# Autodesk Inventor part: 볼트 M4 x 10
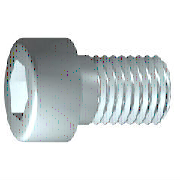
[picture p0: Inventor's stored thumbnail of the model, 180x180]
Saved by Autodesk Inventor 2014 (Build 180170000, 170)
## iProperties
Created: 2012-02
Part Number: 볼트 M4 x 10
Material: 스테인리스강
Description: 6각 소켓 머리 캡 나사
Document SubType Name: Modeling
Standard: ISO 4762
Designer: mduedu
Standard Revision: Fourth edition 2004-03-01
Standards Organization: ISO
Language: ko-KR
Size Designation: M4 x 10
Categories: <MemberInstance><Categories><Category DisplayName="조임쇠" InternalName="e4da775c-781d-43d5-af7c-5136215cf5a6" Mnemonic="FSTN"><Category DisplayName="볼트" InternalN
Density: 8.08 g/cm^3
Appearance: 반광택
IsCustomPart: 0
Author: mduedu
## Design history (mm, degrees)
sketch "스케치1"
  geometry: L1 (-1, 0)-(10, 0); L2 (10, 0)-(10, 2); L3 (10, 2)-(1.75, 2); L4 (1.75, 2)-(1.32, 2); L5 (1.32, 2)-(0, 2); L6 (0, 2)-(0, 3.5); L7 (0, 3.5)-(-4, 3.5); L8 (-4, 3.5)-(-4, 1.732); L9 (-4, 1.732)-(-2, 1.732); L10 (-2, 1.732)-(-1, 0); L11 (-6.8, 0)-(12.8, 0) reference; L12 (0, -0.7)-(0, 4.2) reference; L13 (1.75, 2)-(0, 2)
  constraints: 22 end point, 6 parallel, 2 collinear, 2 perpendicular, 1 horizontal, 1 point on line
  dimensions: "d1" = 8.25 distance from line of L3.end L2 (= GEL); "d2" = 0.42952 distance of L4.end L3.end (computed from GAL); "d3" = 4 distance between parallel lines of L8 L6 (= KOH); "d4" = 2 distance of L8.end L9.end (= INTI); "d5" = 60 deg angle of L10 L1; "d6" = 4 diameter of L3 L1 (= GD); "d7" = 4 diameter of L5 L1 (= BDM); "d8" = 3.4641 diameter of L9 L1 (= 1.1547 x SW); "d9" = 7 diameter of L7 L1 (= KOD); "d26" = 10 distance between parallel lines of L12 L2 (= NLG)
revolve "본체" sketch "스케치1" stored, may be unused: angle "d10" = 90 deg
sketch "스케치2"
  geometry: L1 (0, -4.9)-(0, 4.9) reference; L2 (-4.9, 0)-(4.9, 0) reference; L3 (1.732, 0)-(0.866, -1.5); L4 (0.866, -1.5)-(-0.866, -1.5); L5 (-0.866, -1.5)-(-1.732, 0); L6 (-1.732, 0)-(-0.866, 1.5); L7 (-0.866, 1.5)-(0.866, 1.5); L8 (0.866, 1.5)-(1.732, 0); 2 further points
  constraints: 12 end point, 1 coincident, 1 horizontal alignment, 1 point on line, 12 other
extrude "슬롯" join sketch "스케치2" stored distance "d11" = 10; taper "d12" = 0 deg
workplane "Work Plane1"
fillet "Fillet2" dims "d30" = 0.1 (= R)
body "Solid1"
fillet "모깎기1" dims "d17" = 0.4 (= RR)
feature "스레드" dims "d13" = 8.25 (= GEL), "d14" = 0
chamfer "모따기1" distance "d15" = 0.42941 (= -0.5 x SPD + 0.5 x GD); stored, may be unused: second distance "d16" = 0.42941 (= GUL), angle "d27" = 45 deg
other parameters: "GD" = 4 [user parameter; used in 2 equation terms], "NLG" = 10 [user parameter; used in 1 equation term], "GEL" = 8.25 [user parameter; used in 2 equation terms], "KOD" = 7 [user parameter; used in 1 equation term], "KOH" = 4 [user parameter; used in 1 equation term], "INTI" = 2 [user parameter; used in 1 equation term], "GAL" = 0.42941 (= 0.61345 x PTC) [user parameter; used in 1 equation term], "GUL" = 0.42941 (= 0.61345 x PTC) [user parameter; used in 1 equation term], "BDM" = 4 (= NND) [user parameter; used in 1 equation term], "SW" = 3 [user parameter; used in 2 equation terms], "RR" = 0.4 [user parameter; used in 1 equation term], "SPD" = 3.14117 (= NND - 1.2269 x PTC) [user parameter; used in 1 equation term], "d19" = 0, "d28" = 0, "d29" = 0, "R" = 0.1 [user parameter; used in 1 equation term], "TOA" = 30 deg [user parameter], "GD1" = 3.14117 (= THREADDIA - 1.2269 x PTC) [user parameter], "THREADDIA" = 4 [user parameter; used in 1 equation term], "FAWI" = 45 deg [user parameter], "TPU" = 14.28571 (computed from PTC) [user parameter], "PTC" = 0.7 [user parameter; used in 5 equation terms], "NND" = 4 [user parameter; used in 2 equation terms], "E0" = 3.465 (= 1.155 x SW) [user parameter]
